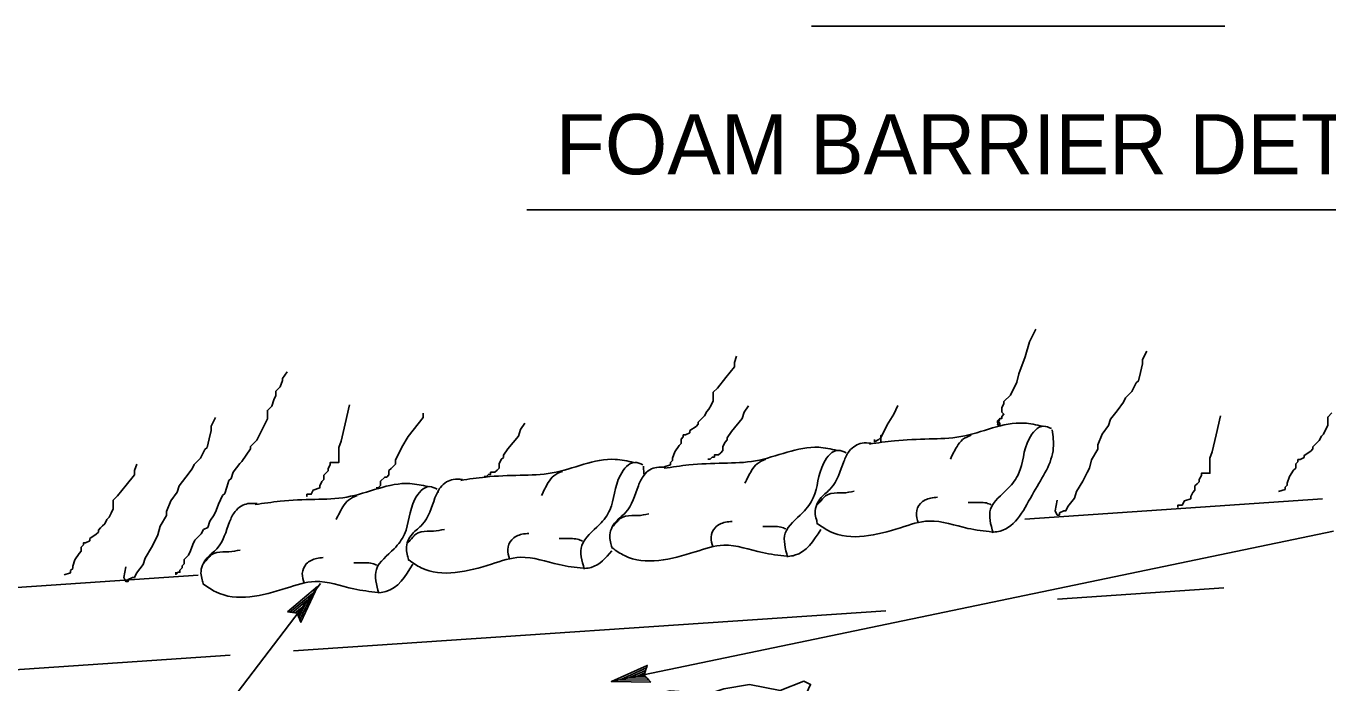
# Model space of a CAD drawing. Extents: x 6708945 to 6710368, y 1871409 to 1872338.
# Drawn here: x 6709648 to 6709843.2, y 1871944.4 to 1872042.8 of the extents above; entities that cross this region are included whole.
import ezdxf

# ---------------------------------------------------------------- set-up
doc = ezdxf.new("R2010")
doc.units = 0
doc.layers.add('57 Undefined', color=7, linetype='Continuous')
doc.layers.add('60 Nongeo Data', color=7, linetype='Continuous')

msp = doc.modelspace()

# ---------------------------------------------------------------- linework, layer by layer
at = {"layer": '57 Undefined'}
for p, q in [((6709765.75, 1872042.79), (6709827.73, 1872042.79)), ((6709723.08, 1872015.26), (6709874.13, 1872015.26)), ((6709735.76, 1871944.57), (6709844.01, 1871967.11)), ((6709642.88, 1871894.69), (6709692.17, 1871959.27))]:
    msp.add_line(p, q, dxfattribs=at)
at = {"layer": '60 Nongeo Data'}
for p, q in [((6709771.06, 1871978.55), (6709771.05, 1871978.65)), ((6709740.63, 1871975.66), (6709740.56, 1871976.84)), ((6709709.79, 1871972.91), (6709709.77, 1871973.21)), ((6709691.7, 1871958.79), (6709691.7, 1871958.79)), ((6709687.18, 1871954.99), (6709687.18, 1871954.99)), ((6709689.22, 1871953.44), (6709689.22, 1871953.44)), ((6709741.14, 1871946.99), (6709741.14, 1871946.99)), ((6709735.76, 1871944.57), (6709735.76, 1871944.57)), ((6709741.66, 1871944.48), (6709741.66, 1871944.48))]:
    msp.add_line(p, q, dxfattribs=at)
for points in [[(6709799.4, 1871997.38), (6709798.44, 1871995.46), (6709797.8, 1871993.23), (6709796.84, 1871990.67), (6709796.52, 1871989.4), (6709795.56, 1871987.48), (6709794.6, 1871986.53), (6709794.6, 1871986.21), (6709794.28, 1871985.57), (6709794.28, 1871984.93), (6709794.6, 1871984.61), (6709794.28, 1871984.29), (6709794.28, 1871983.97), (6709793.96, 1871983.97), (6709793.64, 1871983.65), (6709793.64, 1871983.33), (6709793.96, 1871983.33), (6709793.96, 1871983.33), (6709793.96, 1871983.02), (6709793.64, 1871983.02), (6709793.96, 1871983.97)], [(6709754.53, 1871993.33), (6709754.21, 1871992.38), (6709754.21, 1871991.74), (6709752.93, 1871990.14), (6709751.65, 1871988.55), (6709751.01, 1871987.91), (6709751.01, 1871987.59), (6709751.01, 1871986.95), (6709751.01, 1871986.63), (6709750.69, 1871985.99), (6709750.37, 1871985.36), (6709750.05, 1871985.04), (6709749.73, 1871984.4), (6709749.41, 1871984.08), (6709749.09, 1871983.76), (6709748.77, 1871983.44), (6709748.77, 1871983.12), (6709748.45, 1871982.8), (6709747.49, 1871982.16), (6709747.49, 1871981.85), (6709746.85, 1871981.53), (6709746.53, 1871981.53), (6709746.53, 1871981.21), (6709746.21, 1871980.89), (6709746.21, 1871980.25), (6709745.89, 1871979.93), (6709745.25, 1871978.97), (6709744.93, 1871978.02), (6709744.93, 1871977.7), (6709744.61, 1871977.38), (6709744.61, 1871977.06), (6709744.61, 1871977.06), (6709743.65, 1871976.74)], [(6709816.03, 1871994.08), (6709815.39, 1871992.81), (6709815.39, 1871992.17), (6709815.07, 1871990.89), (6709814.75, 1871989.61), (6709814.43, 1871989.3), (6709813.79, 1871988.02), (6709812.83, 1871987.06), (6709812.51, 1871986.42), (6709811.55, 1871985.15), (6709810.59, 1871983.87), (6709810.27, 1871982.91), (6709809.31, 1871981.64), (6709808.67, 1871980.04), (6709808.67, 1871979.4), (6709807.72, 1871977.81), (6709807.4, 1871976.53), (6709807.08, 1871975.89), (6709806.44, 1871974.61), (6709805.48, 1871973.02), (6709805.16, 1871972.06), (6709804.2, 1871970.79), (6709803.88, 1871970.15), (6709803.56, 1871970.15), (6709802.92, 1871969.83), (6709802.92, 1871969.51), (6709802.92, 1871969.51), (6709802.6, 1871969.51), (6709802.28, 1871970.15), (6709802.6, 1871971.74)], [(6709687.17, 1871990.97), (6709686.43, 1871989.99), (6709686.43, 1871989.67), (6709686.11, 1871988.71), (6709685.47, 1871988.07), (6709685.47, 1871987.43), (6709685.15, 1871986.8), (6709684.83, 1871985.84), (6709684.19, 1871985.2), (6709684.19, 1871983.92), (6709683.55, 1871982.65), (6709683.23, 1871982.01), (6709682.59, 1871980.73), (6709681.63, 1871979.77), (6709681.63, 1871979.45), (6709680.99, 1871978.5), (6709680.35, 1871977.54), (6709680.03, 1871977.22), (6709679.07, 1871975.94), (6709678.75, 1871974.99), (6709678.43, 1871974.67), (6709678.11, 1871973.71), (6709677.79, 1871972.75), (6709677.47, 1871972.43), (6709676.84, 1871971.16), (6709676.52, 1871970.2), (6709676.2, 1871969.56), (6709675.56, 1871968.6), (6709675.24, 1871967.65), (6709674.6, 1871967.33), (6709674.28, 1871966.69), (6709673.32, 1871965.73), (6709673, 1871965.09), (6709672.68, 1871964.14), (6709672.36, 1871963.5), (6709672.04, 1871963.18), (6709671.72, 1871962.86), (6709671.72, 1871962.22), (6709671.4, 1871961.9), (6709671.4, 1871961.58), (6709671.08, 1871961.26), (6709671.08, 1871960.95), (6709670.76, 1871960.95), (6709670.44, 1871960.63), (6709670.44, 1871960.95)], [(6709696.5, 1871986.03), (6709695.86, 1871983.16), (6709695.22, 1871980.6), (6709694.9, 1871979.65), (6709694.9, 1871978.37), (6709694.9, 1871978.05), (6709694.9, 1871977.73), (6709694.9, 1871977.41), (6709694.58, 1871977.41), (6709693.94, 1871977.41), (6709693.62, 1871977.41), (6709693.62, 1871977.09), (6709693.3, 1871976.45), (6709693.3, 1871976.14), (6709692.98, 1871975.82), (6709692.66, 1871975.5), (6709692.66, 1871974.86), (6709692.34, 1871974.54), (6709692.03, 1871973.9), (6709692.03, 1871973.58), (6709691.07, 1871973.26), (6709690.75, 1871972.63), (6709690.43, 1871972.63), (6709690.11, 1871972.63), (6709690.11, 1871972.31), (6709690.11, 1871972.31)], [(6709756.3, 1871985.87), (6709755.66, 1871984.91), (6709755.34, 1871983.96), (6709753.75, 1871982.04), (6709753.11, 1871981.08), (6709753.11, 1871980.76), (6709752.79, 1871980.45), (6709752.47, 1871979.81), (6709752.47, 1871979.49), (6709752.47, 1871979.17), (6709752.15, 1871978.85), (6709751.83, 1871978.53), (6709751.51, 1871978.53), (6709751.19, 1871978.53), (6709751.19, 1871978.21), (6709750.87, 1871978.21), (6709750.87, 1871978.21), (6709750.55, 1871977.89), (6709750.23, 1871977.89)], [(6709778.71, 1871985.92), (6709778.07, 1871984.64), (6709777.11, 1871983.05), (6709776.47, 1871981.77), (6709776.15, 1871981.13), (6709776.15, 1871980.5), (6709776.15, 1871981.13), (6709776.15, 1871981.45), (6709776.15, 1871981.13), (6709775.83, 1871980.81), (6709775.19, 1871980.5), (6709775.19, 1871980.81)], [(6709843.77, 1871984.84), (6709843.13, 1871984.2), (6709843.13, 1871983.88), (6709843.13, 1871983.24), (6709843.13, 1871982.93), (6709842.81, 1871982.29), (6709842.49, 1871981.65), (6709842.18, 1871981.33), (6709841.86, 1871980.69), (6709841.54, 1871980.37), (6709841.22, 1871980.05), (6709840.9, 1871979.73), (6709840.9, 1871979.42), (6709840.58, 1871979.1), (6709839.62, 1871978.46), (6709839.62, 1871978.14), (6709838.98, 1871977.82), (6709838.66, 1871977.82), (6709838.66, 1871977.5), (6709838.34, 1871977.18), (6709838.34, 1871976.54), (6709838.02, 1871976.22), (6709837.38, 1871975.27), (6709837.06, 1871974.31), (6709837.06, 1871973.99), (6709836.74, 1871973.67), (6709836.74, 1871973.35), (6709836.74, 1871973.35), (6709835.78, 1871973.03)], [(6709676.41, 1871984.11), (6709675.77, 1871982.83), (6709675.77, 1871982.19), (6709675.45, 1871980.92), (6709675.14, 1871979.64), (6709674.82, 1871979.32), (6709674.18, 1871978.05), (6709673.22, 1871977.09), (6709672.9, 1871976.45), (6709671.94, 1871975.17), (6709670.98, 1871973.9), (6709670.66, 1871972.94), (6709669.7, 1871971.66), (6709669.06, 1871970.07), (6709669.06, 1871969.43), (6709668.1, 1871967.83), (6709667.78, 1871966.56), (6709667.46, 1871965.92), (6709666.82, 1871964.64), (6709665.86, 1871963.05), (6709665.54, 1871962.09), (6709664.58, 1871960.81), (6709664.26, 1871960.17), (6709663.94, 1871960.17), (6709663.3, 1871959.86), (6709663.3, 1871959.54), (6709663.3, 1871959.54), (6709662.98, 1871959.54), (6709662.66, 1871960.17), (6709662.98, 1871961.77)], [(6709707.52, 1871984.78), (6709707.52, 1871984.15), (6709705.28, 1871981.27), (6709704.32, 1871979.68), (6709703.37, 1871977.76), (6709703.37, 1871977.13), (6709702.73, 1871976.49), (6709702.41, 1871976.17), (6709702.41, 1871975.85), (6709702.41, 1871975.53), (6709702.09, 1871975.21), (6709701.77, 1871975.21), (6709701.13, 1871974.57), (6709701.13, 1871974.25), (6709701.13, 1871973.93), (6709700.81, 1871973.61), (6709700.81, 1871973.61), (6709700.49, 1871973.61)], [(6709722.77, 1871983.26), (6709722.13, 1871982.31), (6709721.81, 1871981.35), (6709720.21, 1871979.43), (6709719.57, 1871978.48), (6709719.57, 1871978.16), (6709719.25, 1871977.84), (6709718.93, 1871977.2), (6709718.93, 1871976.88), (6709718.93, 1871976.56), (6709718.61, 1871976.24), (6709718.29, 1871975.92), (6709717.97, 1871975.92), (6709717.65, 1871975.92), (6709717.65, 1871975.61), (6709717.33, 1871975.61), (6709717.33, 1871975.61), (6709717.01, 1871975.29), (6709716.69, 1871975.29)], [(6709827.07, 1871984.4), (6709826.43, 1871981.53), (6709825.79, 1871978.97), (6709825.47, 1871978.02), (6709825.47, 1871976.74), (6709825.47, 1871976.42), (6709825.47, 1871976.1), (6709825.47, 1871975.78), (6709825.15, 1871975.78), (6709824.51, 1871975.78), (6709824.19, 1871975.78), (6709824.19, 1871975.46), (6709823.87, 1871974.83), (6709823.87, 1871974.51), (6709823.55, 1871974.19), (6709823.23, 1871973.87), (6709823.23, 1871973.23), (6709822.92, 1871972.91), (6709822.6, 1871972.27), (6709822.6, 1871971.95), (6709821.64, 1871971.63), (6709821.32, 1871971), (6709821, 1871971), (6709820.68, 1871971), (6709820.68, 1871970.68), (6709820.68, 1871970.68)], [(6709664.6, 1871977.16), (6709664.28, 1871976.2), (6709664.28, 1871975.56), (6709663, 1871973.97), (6709661.72, 1871972.37), (6709661.09, 1871971.73), (6709661.09, 1871971.41), (6709661.09, 1871970.78), (6709661.09, 1871970.46), (6709660.77, 1871969.82), (6709660.45, 1871969.18), (6709660.13, 1871968.86), (6709659.81, 1871968.22), (6709659.49, 1871967.9), (6709659.17, 1871967.59), (6709658.85, 1871967.27), (6709658.85, 1871966.95), (6709658.53, 1871966.63), (6709657.57, 1871965.99), (6709657.57, 1871965.67), (6709656.93, 1871965.35), (6709656.61, 1871965.35), (6709656.61, 1871965.03), (6709656.29, 1871964.71), (6709656.29, 1871964.08), (6709655.97, 1871963.76), (6709655.33, 1871962.8), (6709655.01, 1871961.84), (6709655.01, 1871961.52), (6709654.69, 1871961.2), (6709654.69, 1871960.88), (6709654.69, 1871960.88), (6709653.73, 1871960.56)], [(6709797.75, 1871968.92), (6709842.33, 1871971.95)], [(6709646.63, 1871958.67), (6709673.79, 1871960.51)], [(6709802.63, 1871956.92), (6709827.55, 1871958.61)], [(6709688.12, 1871949.15), (6709776.89, 1871955.17)], [(6709626.43, 1871944.96), (6709678.6, 1871948.5)], [(6709735.78, 1871941.5), (6709744.54, 1871943.18), (6709747.24, 1871942.97), (6709749.4, 1871942.44), (6709752.63, 1871943.46), (6709756.46, 1871944.11), (6709761.04, 1871943.21), (6709764.6, 1871944.61), (6709765.62, 1871944.13), (6709760.91, 1871933.87)]]:
    msp.add_lwpolyline(points, dxfattribs=at)
for points in [[(6709687.18, 1871954.99), (6709691.7, 1871958.79), (6709689.22, 1871953.44), (6709689.07, 1871953.81), (6709690.89, 1871957.73), (6709687.57, 1871954.95), (6709687.97, 1871954.9), (6709690.08, 1871956.69), (6709688.92, 1871954.18), (6709688.78, 1871954.55), (6709689.28, 1871955.63), (6709688.36, 1871954.86), (6709688.67, 1871954.82), (6709689.22, 1871953.44), (6709688.67, 1871954.82)], [(6709741.66, 1871944.48), (6709735.76, 1871944.57), (6709741.14, 1871946.99), (6709741.01, 1871946.62), (6709737.07, 1871944.84), (6709741.39, 1871944.77), (6709741.13, 1871945.06), (6709738.36, 1871945.1), (6709740.88, 1871946.24), (6709740.75, 1871945.87), (6709739.66, 1871945.37), (6709740.86, 1871945.36), (6709740.65, 1871945.58), (6709741.14, 1871946.99), (6709740.65, 1871945.58)]]:
    msp.add_lwpolyline(points, close=True, dxfattribs=at)
for points in [[(6709800.36, 1871982.83), (6709797.62, 1871983.29), (6709788.13, 1871981.26), (6709783.37, 1871980.92), (6709778.17, 1871980.64), (6709774.44, 1871980.15)], [(6709786.57, 1871977.9), (6709787.57, 1871979.81), (6709788.4, 1871980.82), (6709789.69, 1871981.5)], [(6709792.96, 1871966.85), (6709792.6, 1871970.41), (6709795.24, 1871973.52), (6709796.8, 1871975.71), (6709798.38, 1871980.94), (6709800.54, 1871982.83), (6709801.73, 1871982.47)], [(6709793.05, 1871966.94), (6709794.01, 1871967.11), (6709799.08, 1871972.97), (6709802, 1871979.55), (6709801.84, 1871982.27)], [(6709769.57, 1871979.21), (6709766.83, 1871979.67), (6709757.34, 1871977.63), (6709752.58, 1871977.29), (6709747.38, 1871977.02), (6709743.65, 1871976.52)], [(6709762.17, 1871963.22), (6709761.81, 1871966.79), (6709764.45, 1871969.89), (6709766.01, 1871972.08), (6709767.59, 1871977.32), (6709769.75, 1871979.21), (6709770.94, 1871978.84)], [(6709766.66, 1871968.13), (6709766.48, 1871968.86), (6709766.3, 1871969.86), (6709767.21, 1871972.15), (6709768.67, 1871973.52), (6709770.59, 1871977.54), (6709771.41, 1871979.09), (6709772.33, 1871979.91), (6709773.33, 1871980.28), (6709774.7, 1871980.28)], [(6709739.08, 1871977.4), (6709736.34, 1871977.85), (6709726.86, 1871975.82), (6709722.1, 1871975.48), (6709716.89, 1871975.21), (6709713.16, 1871974.71)], [(6709731.68, 1871961.41), (6709731.32, 1871964.97), (6709733.97, 1871968.08), (6709735.52, 1871970.27), (6709737.1, 1871975.5), (6709739.26, 1871977.4), (6709740.45, 1871977.03)], [(6709755.78, 1871974.28), (6709756.78, 1871976.19), (6709757.61, 1871977.2), (6709758.9, 1871977.87)], [(6709725.29, 1871972.46), (6709726.29, 1871974.37), (6709727.12, 1871975.39), (6709728.41, 1871976.06)], [(6709735.87, 1871964.5), (6709735.69, 1871965.23), (6709735.51, 1871966.24), (6709736.42, 1871968.52), (6709737.88, 1871969.89), (6709739.8, 1871973.91), (6709740.62, 1871975.46), (6709741.54, 1871976.29), (6709742.54, 1871976.65), (6709743.91, 1871976.65)], [(6709708.29, 1871973.77), (6709705.55, 1871974.23), (6709696.07, 1871972.2), (6709691.31, 1871971.86), (6709686.1, 1871971.58), (6709682.37, 1871971.09)], [(6709700.89, 1871957.79), (6709700.53, 1871961.35), (6709703.18, 1871964.46), (6709704.73, 1871966.65), (6709706.31, 1871971.88), (6709708.47, 1871973.77), (6709709.66, 1871973.41)], [(6709705.39, 1871962.69), (6709705.2, 1871963.42), (6709705.02, 1871964.43), (6709705.93, 1871966.71), (6709707.4, 1871968.08), (6709709.31, 1871972.1), (6709710.13, 1871973.65), (6709711.05, 1871974.47), (6709712.05, 1871974.84), (6709713.42, 1871974.84)], [(6709766.66, 1871971.1), (6709767.39, 1871971.92), (6709767.85, 1871972.38), (6709769.59, 1871972.83), (6709770.5, 1871972.83), (6709772.14, 1871973.11)], [(6709674.6, 1871959.07), (6709674.41, 1871959.8), (6709674.23, 1871960.8), (6709675.14, 1871963.09), (6709676.61, 1871964.46), (6709678.52, 1871968.48), (6709679.34, 1871970.03), (6709680.26, 1871970.85), (6709681.26, 1871971.22), (6709682.63, 1871971.22)], [(6709694.5, 1871968.84), (6709695.5, 1871970.75), (6709696.33, 1871971.76), (6709697.62, 1871972.44)], [(6709781.75, 1871968.36), (6709781.49, 1871969.81), (6709782.08, 1871971.25), (6709783.63, 1871972.06), (6709784.64, 1871972.19)], [(6709792.69, 1871971.05), (6709791.96, 1871971.32), (6709790.95, 1871971.41), (6709789.22, 1871971.41)], [(6709735.87, 1871967.7), (6709736.6, 1871968.52), (6709737.06, 1871968.98), (6709738.8, 1871969.43), (6709739.71, 1871969.43), (6709741.35, 1871969.71)], [(6709705.24, 1871965.36), (6709705.97, 1871966.18), (6709706.42, 1871966.64), (6709708.16, 1871967.09), (6709709.07, 1871967.09), (6709710.71, 1871967.37)], [(6709750.97, 1871964.74), (6709750.7, 1871966.19), (6709751.29, 1871967.62), (6709752.84, 1871968.44), (6709753.85, 1871968.57)], [(6709761.9, 1871967.43), (6709761.17, 1871967.7), (6709760.16, 1871967.79), (6709758.43, 1871967.79)], [(6709762.26, 1871963.31), (6709763.22, 1871963.48), (6709767.16, 1871967.34)], [(6709766.67, 1871968.22), (6709768.51, 1871967.06), (6709779.08, 1871967.61), (6709783.4, 1871968.62), (6709789.2, 1871967.52), (6709792.83, 1871966.97)], [(6709720.48, 1871962.93), (6709720.21, 1871964.37), (6709720.81, 1871965.81), (6709722.35, 1871966.63), (6709723.36, 1871966.76)], [(6709731.41, 1871965.61), (6709730.68, 1871965.89), (6709729.68, 1871965.98), (6709727.94, 1871965.98)], [(6709674.6, 1871962.26), (6709675.33, 1871963.09), (6709675.78, 1871963.54), (6709677.52, 1871964), (6709678.43, 1871964), (6709680.08, 1871964.27)], [(6709731.78, 1871961.5), (6709732.74, 1871961.67), (6709735.81, 1871964.13)], [(6709735.88, 1871964.59), (6709737.72, 1871963.43), (6709748.29, 1871963.99), (6709752.61, 1871965), (6709758.41, 1871963.89), (6709762.04, 1871963.35)], [(6709689.69, 1871959.3), (6709689.42, 1871960.75), (6709690.02, 1871962.19), (6709691.56, 1871963), (6709692.57, 1871963.13)], [(6709700.62, 1871961.99), (6709699.89, 1871962.26), (6709698.89, 1871962.35), (6709697.15, 1871962.35)], [(6709700.99, 1871957.88), (6709701.95, 1871958.05), (6709705.98, 1871962.14)], [(6709705.39, 1871962.78), (6709707.23, 1871961.62), (6709717.8, 1871962.17), (6709722.12, 1871963.19), (6709727.92, 1871962.08), (6709731.55, 1871961.53)], [(6709674.6, 1871959.16), (6709676.44, 1871958), (6709687.01, 1871958.55), (6709691.34, 1871959.56), (6709697.13, 1871958.46), (6709700.76, 1871957.91)]]:
    msp.add_spline(points, degree=3, dxfattribs=at)

# ---------------------------------------------------------------- texts
at = {"layer": '57 Undefined'}
msp.add_text('FOAM BARRIER DETAIL', height=9, dxfattribs=at).set_placement((6709727.43, 1872020.58))

doc.saveas('drawing.dxf')
